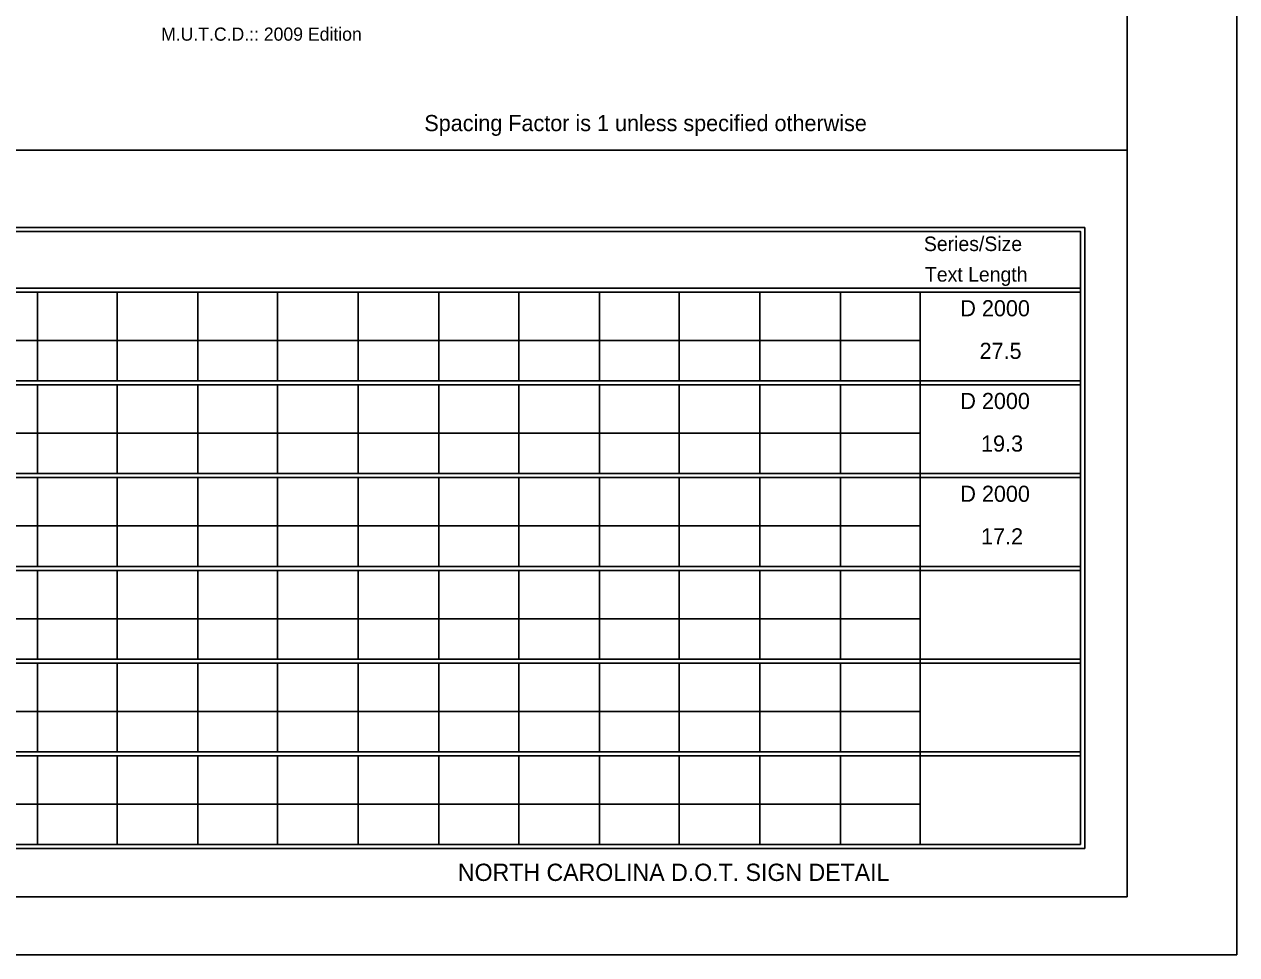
# Model space of a CAD drawing. Extents: x 1788.1 to 1851.2, y 237.2 to 283.4.
# Drawn here: x 1804.46 to 1818.27, y 262.55 to 273.15 of the extents above; entities that cross this region are included whole.
import ezdxf

# ---------------------------------------------------------------- set-up
doc = ezdxf.new("R2010")
doc.units = 0
for name, color, linetype in [('GSDIMS', 7, 'Continuous'), ('Old_Level_2', 7, 'Continuous'), ('Sheet Plot Border Outside CELL', 7, 'Continuous')]:
    doc.layers.add(name, color=color, linetype=linetype)

msp = doc.modelspace()

# ---------------------------------------------------------------- linework, layer by layer
at = {"layer": 'Old_Level_2'}
for p, q in [((1799.855, 271.718), (1817.019, 271.718)), ((1789.056, 270.146), (1810.834, 270.146)), ((1789.056, 270.1), (1810.834, 270.1)), ((1804.61, 270.1), (1804.61, 269.089)), ((1805.519, 270.1), (1805.519, 269.089)), ((1806.437, 270.1), (1806.437, 269.089)), ((1807.346, 270.1), (1807.346, 269.089)), ((1808.265, 270.1), (1808.265, 269.089)), ((1809.183, 270.1), (1809.183, 269.089)), ((1809.859, 270.146), (1816.491, 270.146)), ((1809.859, 270.1), (1816.491, 270.1)), ((1810.092, 270.1), (1810.092, 269.089)), ((1810.092, 270.1), (1810.092, 269.089)), ((1811.01, 270.1), (1811.01, 269.089)), ((1811.919, 270.1), (1811.919, 269.089)), ((1812.837, 270.1), (1812.837, 269.089)), ((1813.755, 270.1), (1813.755, 269.089)), ((1814.664, 270.1), (1814.664, 263.975)), ((1789.974, 269.548), (1810.834, 269.548)), ((1809.859, 269.548), (1814.664, 269.548)), ((1814.664, 269.339), (1814.664, 269.089)), ((1789.056, 269.089), (1810.834, 269.089)), ((1789.056, 269.043), (1810.834, 269.043)), ((1804.61, 269.043), (1804.61, 268.033)), ((1805.519, 269.043), (1805.519, 268.033)), ((1806.437, 269.043), (1806.437, 268.033)), ((1807.346, 269.043), (1807.346, 268.033)), ((1808.265, 269.043), (1808.265, 268.033)), ((1809.183, 269.043), (1809.183, 268.033)), ((1809.859, 269.089), (1816.491, 269.089)), ((1809.859, 269.043), (1816.491, 269.043)), ((1810.092, 269.043), (1810.092, 268.033)), ((1810.092, 269.043), (1810.092, 268.033)), ((1811.01, 269.043), (1811.01, 268.033)), ((1811.919, 269.043), (1811.919, 268.033)), ((1812.837, 269.043), (1812.837, 268.033)), ((1813.755, 269.043), (1813.755, 268.033)), ((1814.664, 269.043), (1814.664, 268.564)), ((1789.974, 268.492), (1810.834, 268.492)), ((1809.859, 268.492), (1814.664, 268.492)), ((1814.664, 268.362), (1814.664, 268.033)), ((1789.056, 268.033), (1810.834, 268.033)), ((1809.859, 268.033), (1816.491, 268.033)), ((1789.056, 267.987), (1810.834, 267.987)), ((1804.61, 267.987), (1804.61, 266.976)), ((1805.519, 267.987), (1805.519, 266.976)), ((1806.437, 267.987), (1806.437, 266.976)), ((1807.346, 267.987), (1807.346, 266.976)), ((1808.265, 267.987), (1808.265, 266.976)), ((1809.183, 267.987), (1809.183, 266.976)), ((1809.859, 267.987), (1816.491, 267.987)), ((1810.092, 267.987), (1810.092, 266.976)), ((1810.092, 267.987), (1810.092, 266.976)), ((1811.01, 267.987), (1811.01, 266.976)), ((1811.919, 267.987), (1811.919, 266.976)), ((1812.837, 267.987), (1812.837, 266.976)), ((1813.755, 267.987), (1813.755, 266.976)), ((1814.664, 267.987), (1814.664, 267.576)), ((1789.974, 267.436), (1810.834, 267.436)), ((1809.859, 267.436), (1814.664, 267.436)), ((1814.664, 267.274), (1814.664, 266.976)), ((1789.056, 266.976), (1810.834, 266.976)), ((1789.056, 266.93), (1810.834, 266.93)), ((1804.61, 266.93), (1804.61, 265.92)), ((1805.519, 266.93), (1805.519, 265.92)), ((1806.437, 266.93), (1806.437, 265.92)), ((1807.346, 266.93), (1807.346, 265.92)), ((1808.265, 266.93), (1808.265, 265.92)), ((1809.183, 266.93), (1809.183, 265.92)), ((1809.859, 266.976), (1816.491, 266.976)), ((1809.859, 266.93), (1816.491, 266.93)), ((1810.092, 266.93), (1810.092, 265.92)), ((1810.092, 266.93), (1810.092, 265.92)), ((1811.01, 266.93), (1811.01, 265.92)), ((1811.919, 266.93), (1811.919, 265.92)), ((1812.837, 266.93), (1812.837, 265.92)), ((1813.755, 266.93), (1813.755, 265.92)), ((1814.664, 266.93), (1814.664, 266.488)), ((1789.974, 266.379), (1810.834, 266.379)), ((1809.859, 266.379), (1814.664, 266.379)), ((1814.664, 266.185), (1814.664, 265.92)), ((1804.61, 266.037), (1804.61, 265.92)), ((1805.519, 266.037), (1805.519, 265.92)), ((1806.437, 266.037), (1806.437, 265.92)), ((1807.346, 266.037), (1807.346, 265.92)), ((1808.265, 266.037), (1808.265, 265.92)), ((1809.183, 266.037), (1809.183, 265.92)), ((1810.092, 266.037), (1810.092, 265.92)), ((1810.092, 266.037), (1810.092, 265.92)), ((1811.01, 266.037), (1811.01, 265.92)), ((1811.919, 266.037), (1811.919, 265.92)), ((1812.837, 266.037), (1812.837, 265.92)), ((1813.755, 266.037), (1813.755, 265.92)), ((1814.664, 266.037), (1814.664, 265.92)), ((1789.056, 265.92), (1810.834, 265.92)), ((1789.056, 265.92), (1810.834, 265.92)), ((1789.056, 265.874), (1810.834, 265.874)), ((1789.056, 265.874), (1810.834, 265.874)), ((1804.61, 265.874), (1804.61, 264.929)), ((1804.61, 265.874), (1804.61, 264.863)), ((1805.519, 265.874), (1805.519, 264.929)), ((1805.519, 265.874), (1805.519, 264.863)), ((1806.437, 265.874), (1806.437, 264.929)), ((1806.437, 265.874), (1806.437, 264.863)), ((1807.346, 265.874), (1807.346, 264.929)), ((1807.346, 265.874), (1807.346, 264.863)), ((1808.265, 265.874), (1808.265, 264.929)), ((1808.265, 265.874), (1808.265, 264.863)), ((1809.183, 265.874), (1809.183, 264.929)), ((1809.183, 265.874), (1809.183, 264.863)), ((1809.859, 265.92), (1816.491, 265.92)), ((1809.859, 265.92), (1816.491, 265.92)), ((1809.859, 265.874), (1816.491, 265.874)), ((1809.859, 265.874), (1816.491, 265.874)), ((1810.092, 265.874), (1810.092, 264.929)), ((1810.092, 265.874), (1810.092, 264.863)), ((1810.092, 265.874), (1810.092, 264.929)), ((1810.092, 265.874), (1810.092, 264.863)), ((1811.01, 265.874), (1811.01, 264.929)), ((1811.01, 265.874), (1811.01, 264.863)), ((1811.919, 265.874), (1811.919, 264.929)), ((1811.919, 265.874), (1811.919, 264.863)), ((1812.837, 265.874), (1812.837, 264.929)), ((1812.837, 265.874), (1812.837, 264.863)), ((1813.755, 265.874), (1813.755, 264.929)), ((1813.755, 265.874), (1813.755, 264.863)), ((1814.664, 265.874), (1814.664, 265.419)), ((1814.664, 265.874), (1814.664, 265.419)), ((1789.974, 265.323), (1810.834, 265.323)), ((1789.974, 265.323), (1810.834, 265.323)), ((1809.859, 265.323), (1814.664, 265.323)), ((1809.859, 265.323), (1814.426, 265.323)), ((1814.664, 265.157), (1814.664, 264.929)), ((1814.664, 265.157), (1814.664, 264.863)), ((1804.61, 264.981), (1804.61, 264.863)), ((1805.519, 264.981), (1805.519, 264.863)), ((1806.437, 264.981), (1806.437, 264.863)), ((1807.346, 264.981), (1807.346, 264.863)), ((1808.265, 264.981), (1808.265, 264.863)), ((1809.183, 264.981), (1809.183, 264.863)), ((1810.092, 264.981), (1810.092, 264.863)), ((1810.092, 264.981), (1810.092, 264.863)), ((1811.01, 264.981), (1811.01, 264.863)), ((1811.919, 264.981), (1811.919, 264.863)), ((1812.837, 264.981), (1812.837, 264.863)), ((1813.755, 264.981), (1813.755, 264.863)), ((1814.664, 264.981), (1814.664, 264.863)), ((1789.056, 264.863), (1810.834, 264.863)), ((1789.056, 264.863), (1810.834, 264.863)), ((1809.859, 264.863), (1816.491, 264.863)), ((1809.859, 264.863), (1816.491, 264.863)), ((1789.056, 264.817), (1810.834, 264.817)), ((1789.056, 264.817), (1810.834, 264.817)), ((1804.61, 264.817), (1804.61, 263.807)), ((1804.61, 264.817), (1804.61, 263.807)), ((1805.519, 264.817), (1805.519, 263.807)), ((1805.519, 264.817), (1805.519, 263.807)), ((1806.437, 264.817), (1806.437, 263.807)), ((1806.437, 264.817), (1806.437, 263.807)), ((1807.346, 264.817), (1807.346, 263.807)), ((1807.346, 264.817), (1807.346, 263.807)), ((1808.265, 264.817), (1808.265, 263.807)), ((1808.265, 264.817), (1808.265, 263.807)), ((1809.183, 264.817), (1809.183, 263.807)), ((1809.183, 264.817), (1809.183, 263.807)), ((1809.859, 264.817), (1816.491, 264.817)), ((1809.859, 264.817), (1816.491, 264.817)), ((1810.092, 264.817), (1810.092, 263.807)), ((1810.092, 264.817), (1810.092, 263.807)), ((1810.092, 264.817), (1810.092, 263.807)), ((1810.092, 264.817), (1810.092, 263.807)), ((1811.01, 264.817), (1811.01, 263.807)), ((1811.01, 264.817), (1811.01, 263.807)), ((1811.919, 264.817), (1811.919, 263.807)), ((1811.919, 264.817), (1811.919, 263.807)), ((1812.837, 264.817), (1812.837, 263.807)), ((1812.837, 264.817), (1812.837, 263.807)), ((1813.755, 264.817), (1813.755, 263.807)), ((1813.755, 264.817), (1813.755, 263.807)), ((1814.664, 264.817), (1814.664, 264.392)), ((1814.664, 264.817), (1814.664, 264.392)), ((1789.974, 264.266), (1810.834, 264.266)), ((1789.974, 264.266), (1810.834, 264.266)), ((1809.859, 264.266), (1814.664, 264.266)), ((1809.859, 264.266), (1814.488, 264.266)), ((1814.664, 264.07), (1814.664, 263.807)), ((1814.664, 264.07), (1814.664, 263.807)), ((1789.009, 263.761), (1810.834, 263.761)), ((1789.056, 263.807), (1810.834, 263.807)), ((1789.056, 263.807), (1810.834, 263.807)), ((1789.056, 263.761), (1810.834, 263.761)), ((1809.859, 263.807), (1816.491, 263.807)), ((1809.859, 263.807), (1816.491, 263.807)), ((1809.859, 263.761), (1816.538, 263.761)), ((1809.859, 263.761), (1816.491, 263.761))]:
    msp.add_line(p, q, dxfattribs=at)
msp.add_lwpolyline([(1788.693, 282.859), (1817.019, 282.859), (1817.019, 263.214), (1788.693, 263.214)], close=True, dxfattribs=at)
for points in [[(1789.009, 264.929), (1789.009, 270.834), (1810.834, 270.834)], [(1789.056, 264.929), (1789.056, 270.789), (1810.834, 270.789)], [(1809.859, 270.834), (1816.538, 270.834), (1816.538, 264.929)], [(1809.859, 270.789), (1816.491, 270.789), (1816.491, 264.929)], [(1816.491, 266.037), (1816.491, 263.807)], [(1816.538, 266.037), (1816.538, 263.761)]]:
    msp.add_lwpolyline(points, dxfattribs=at)
at = {"layer": 'Sheet Plot Border Outside CELL'}
msp.add_lwpolyline([(1818.269, 283.406), (1788.097, 283.406), (1788.097, 262.552), (1818.269, 262.552)], close=True, dxfattribs=at)

# ---------------------------------------------------------------- texts
at = {"layer": 'GSDIMS'}
msp.add_text('M.U.T.C.D.:: 2009 Edition', height=0.15, dxfattribs=at).set_placement((1806.019, 272.963))
at = {"layer": 'Old_Level_2'}
for s, height, p in [('Spacing Factor is 1 unless specified otherwise', 0.18373, (1809.017, 271.933)), ('Series/Size', 0.16535, (1814.706, 270.567)), ('Text Length', 0.16535, (1814.718, 270.219)), ('NORTH CAROLINA D.O.T. SIGN DETAIL', 0.19685, (1809.399, 263.393))]:
    msp.add_text(s, height=height, rotation=360, dxfattribs=at).set_placement(p)
for s, p in [('D 2000', (1815.121, 269.824)), ('27.5', (1815.34, 269.339)), ('D 2000', (1815.121, 268.768)), ('19.3', (1815.357, 268.283)), ('D 2000', (1815.121, 267.711)), ('17.2', (1815.357, 267.226))]:
    msp.add_text(s, height=0.1837, dxfattribs=at).set_placement(p)

doc.saveas('drawing.dxf')
